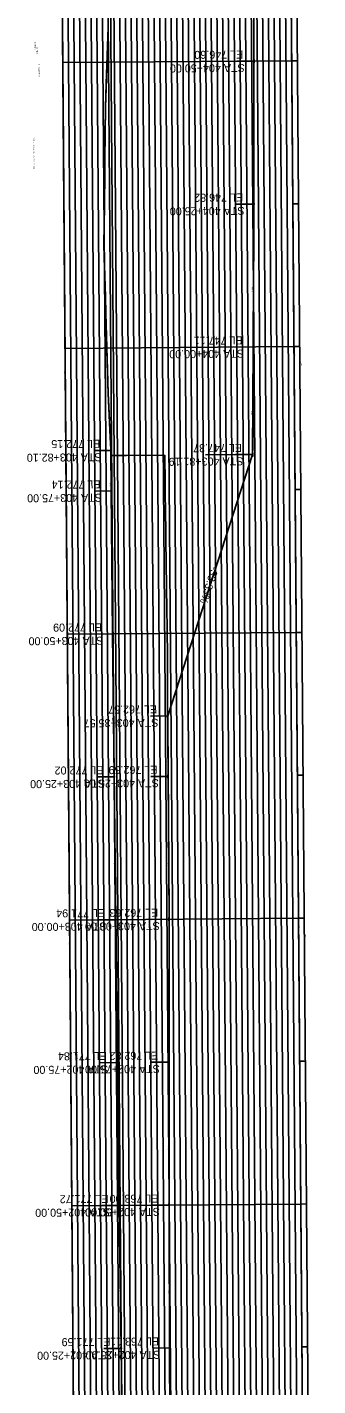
# Model space of a CAD drawing. Extents: x 592274 to 721355, y 141734 to 173089.
# Drawn here: x 593585.6 to 593636.4, y 171859.7 to 172097.4 of the extents above; entities that cross this region are included whole.
import ezdxf

# ---------------------------------------------------------------- set-up
doc = ezdxf.new("R2010")
doc.units = 0
for name, color, linetype in [('B_MISC', 7, 'Continuous'), ('E_PROF_Grid', 7, 'Continuous'), ('E_PROF_GridMin', 7, 'Continuous'), ('P_E_PROF', 7, 'Continuous'), ('P_PROF', 7, 'Continuous'), ('P_PROF_Reference', 7, 'Continuous'), ('P_PROF_Text', 7, 'Continuous'), ('P_PROF_VPINotes', 7, 'Continuous')]:
    doc.layers.add(name, color=color, linetype=linetype)

msp = doc.modelspace()

# ---------------------------------------------------------------- linework, layer by layer
at = {"layer": 'B_MISC'}
msp.add_line((593598.32, 172330.8), (593603.79, 171641.29), dxfattribs=at)
at = {"layer": 'E_PROF_Grid'}
msp.add_lwpolyline([(593636.37, 171641.54), (593629.11, 172558.84), (593628.11, 172558.83), (593635.37, 171641.54)], close=True, dxfattribs=at)
for points in [[(593595.38, 171641.22), (593588.25, 172541.19)], [(593605.37, 171641.3), (593598.25, 172541.27)], [(593615.37, 171641.38), (593608.24, 172541.35)], [(593625.37, 171641.46), (593618.24, 172541.43)], [(593635.37, 171641.54), (593628.24, 172541.51)], [(593632.21, 172041.52), (593592.21, 172041.21)], [(593633.21, 172041.53), (593632.21, 172041.52)], [(593633.21, 172041.53), (593632.21, 172041.52)], [(593633.21, 172041.53), (593632.21, 172041.52)], [(593633, 171941.53), (593593, 171941.21)], [(593634, 171941.54), (593633, 171941.53)], [(593634, 171941.54), (593633, 171941.53)], [(593634, 171941.54), (593633, 171941.53)]]:
    msp.add_lwpolyline(points, dxfattribs=at)
at = {"layer": 'E_PROF_GridMin'}
for points in [[(593596.38, 171641.23), (593589.25, 172541.2)], [(593597.37, 171641.24), (593590.25, 172541.21)], [(593598.37, 171641.24), (593591.25, 172541.22)], [(593599.37, 171641.25), (593592.25, 172541.22)], [(593600.37, 171641.26), (593593.25, 172541.23)], [(593601.37, 171641.27), (593594.25, 172541.24)], [(593602.37, 171641.28), (593595.25, 172541.25)], [(593603.37, 171641.28), (593596.25, 172541.26)], [(593604.37, 171641.29), (593597.25, 172541.26)], [(593606.37, 171641.31), (593599.25, 172541.28)], [(593607.37, 171641.32), (593600.25, 172541.29)], [(593608.37, 171641.32), (593601.25, 172541.29)], [(593609.37, 171641.33), (593602.25, 172541.3)], [(593610.37, 171641.34), (593603.25, 172541.31)], [(593611.37, 171641.35), (593604.25, 172541.32)], [(593612.37, 171641.35), (593605.24, 172541.33)], [(593613.37, 171641.36), (593606.24, 172541.33)], [(593614.37, 171641.37), (593607.24, 172541.34)], [(593616.37, 171641.39), (593609.24, 172541.36)], [(593617.37, 171641.39), (593610.24, 172541.37)], [(593618.37, 171641.4), (593611.24, 172541.37)], [(593619.37, 171641.41), (593612.24, 172541.38)], [(593620.37, 171641.42), (593613.24, 172541.39)], [(593621.37, 171641.43), (593614.24, 172541.4)], [(593622.37, 171641.43), (593615.24, 172541.41)], [(593623.37, 171641.44), (593616.24, 172541.41)], [(593624.37, 171641.45), (593617.24, 172541.42)], [(593626.37, 171641.47), (593619.24, 172541.44)], [(593627.37, 171641.47), (593620.24, 172541.45)], [(593628.37, 171641.48), (593621.24, 172541.45)], [(593629.37, 171641.49), (593622.24, 172541.46)], [(593630.37, 171641.5), (593623.24, 172541.47)], [(593631.37, 171641.51), (593624.24, 172541.48)], [(593632.37, 171641.51), (593625.24, 172541.48)], [(593633.37, 171641.52), (593626.24, 172541.49)], [(593634.37, 171641.53), (593627.24, 172541.5)], [(593631.81, 172091.52), (593591.81, 172091.21)], [(593632.81, 172091.53), (593631.81, 172091.52)], [(593633.01, 172066.53), (593632.01, 172066.52)], [(593633.4, 172016.53), (593632.4, 172016.53)], [(593632.6, 171991.53), (593592.6, 171991.21)], [(593633.6, 171991.53), (593632.6, 171991.53)], [(593633.8, 171966.53), (593632.8, 171966.53)], [(593634.2, 171916.54), (593633.2, 171916.53)], [(593633.39, 171891.53), (593593.39, 171891.21)], [(593634.39, 171891.54), (593633.39, 171891.53)], [(593634.59, 171866.54), (593633.59, 171866.53)]]:
    msp.add_lwpolyline(points, dxfattribs=at)
at = {"layer": 'P_E_PROF'}
for points in [[(593599.39, 172086.68), (593599.73, 172097.41)], [(593599.41, 172087.48), (593599.73, 172097.41)], [(593599.73, 172097.41), (593599.71, 172099.18)], [(593625.21, 172093.96), (593625.21, 172098.96)], [(593625.21, 172088.96), (593625.21, 172093.96)], [(593625.21, 172083.96), (593625.21, 172088.96)], [(593599.28, 172083.4), (593599.41, 172087.48)], [(593599.28, 172083.4), (593599.39, 172086.68)], [(593599.17, 172074.21), (593599.28, 172083.4)], [(593599.18, 172074.9), (593599.28, 172083.4)], [(593625.21, 172078.95), (593625.21, 172083.96)], [(593625.2, 172073.95), (593625.21, 172078.95)], [(593599.13, 172071.4), (593599.18, 172074.9)], [(593599.14, 172071.4), (593599.17, 172074.21)], [(593625.19, 172068.95), (593625.2, 172073.95)], [(593599.02, 172062.21), (593599.14, 172071.4)], [(593599.03, 172062.9), (593599.13, 172071.4)], [(593625.18, 172063.95), (593625.19, 172068.95)], [(593598.99, 172059.4), (593599.03, 172062.9)], [(593598.99, 172059.4), (593599.02, 172062.21)], [(593625.17, 172058.94), (593625.18, 172063.95)], [(593599.23, 172050.9), (593598.99, 172059.4)], [(593599.25, 172050.21), (593598.99, 172059.4)], [(593625.15, 172053.94), (593625.17, 172058.94)], [(593625.13, 172048.94), (593625.15, 172053.94)], [(593599.32, 172047.4), (593599.23, 172050.9)], [(593599.33, 172047.4), (593599.25, 172050.21)], [(593625.11, 172043.94), (593625.13, 172048.94)], [(593599.6, 172037.48), (593599.32, 172047.4)], [(593599.62, 172036.68), (593599.33, 172047.4)], [(593625.08, 172038.93), (593625.11, 172043.94)], [(593625.06, 172033.93), (593625.08, 172038.93)], [(593599.71, 172033.41), (593599.6, 172037.48)], [(593599.72, 172033.41), (593599.62, 172036.68)], [(593600.09, 172025.65), (593599.71, 172033.41)], [(593600.12, 172025.02), (593599.72, 172033.41)], [(593625.03, 172028.93), (593625.06, 172033.93)], [(593624.99, 172023.92), (593625.03, 172028.93)], [(593600.24, 172022.46), (593600.09, 172025.65)], [(593600.2, 172023.41), (593600.12, 172025.02)], [(593624.98, 172022.66), (593624.99, 172023.92)], [(593600.23, 172018.97), (593600.2, 172023.41)], [(593602.96, 172022.48), (593600.24, 172022.46)], [(593609.63, 172022.53), (593602.96, 172022.48)], [(593609.63, 172022.51), (593609.63, 172022.53)], [(593609.69, 172017.64), (593609.63, 172022.51)], [(593616.73, 172022.59), (593624.98, 172022.66)], [(593600.25, 172017.49), (593600.23, 172018.97)], [(593600.31, 172011.46), (593600.25, 172017.49)], [(593609.69, 172017.56), (593609.69, 172017.64)], [(593609.78, 172010.99), (593609.69, 172017.56)], [(593600.31, 172010.89), (593600.31, 172011.46)], [(593600.32, 172010.6), (593600.31, 172010.89)], [(593600.35, 172007.63), (593600.32, 172010.6)], [(593609.79, 172010.96), (593609.78, 172010.99)], [(593609.83, 172007.72), (593609.79, 172010.96)], [(593600.36, 172006.56), (593600.35, 172007.63)], [(593609.83, 172007.7), (593609.83, 172007.72)], [(593610, 171995.42), (593609.83, 172007.7)], [(593600.47, 171995.3), (593600.36, 172006.56)], [(593600.5, 171992.73), (593600.47, 171995.3)], [(593610, 171995.37), (593610, 171995.42)], [(593610.04, 171992.58), (593610, 171995.37)], [(593600.5, 171992.49), (593600.5, 171992.73)], [(593600.5, 171991.99), (593600.5, 171992.49)], [(593600.56, 171986.72), (593600.5, 171991.99)], [(593610.04, 171992.57), (593610.04, 171992.58)], [(593610.04, 171992.54), (593610.04, 171992.57)], [(593610.08, 171986.79), (593610.04, 171992.54)], [(593600.56, 171986.38), (593600.56, 171986.72)], [(593600.6, 171982.79), (593600.56, 171986.38)], [(593610.08, 171986.78), (593610.08, 171986.79)], [(593610.1, 171982.86), (593610.08, 171986.78)], [(593600.71, 171972.31), (593600.6, 171982.79)], [(593610.1, 171982.81), (593610.1, 171982.86)], [(593610.18, 171971.4), (593610.1, 171982.81)], [(593600.72, 171971.32), (593600.71, 171972.31)], [(593610.18, 171971.38), (593610.18, 171971.4)], [(593600.73, 171970.99), (593600.72, 171971.32)], [(593600.77, 171967.49), (593600.73, 171970.99)], [(593610.2, 171967.57), (593610.18, 171971.38)], [(593601.02, 171944.68), (593600.77, 171967.49)], [(593610.2, 171967.46), (593610.2, 171967.57)], [(593610.37, 171942.59), (593610.2, 171967.46)], [(593601.05, 171942.51), (593601.02, 171944.68)], [(593601.05, 171942.49), (593601.05, 171942.51)], [(593601.05, 171942.51), (593601.05, 171942.51)], [(593601.25, 171925.41), (593601.05, 171942.49)], [(593610.37, 171942.57), (593610.37, 171942.59)], [(593610.37, 171942.59), (593610.37, 171942.59)], [(593610.37, 171942.49), (593610.37, 171942.57)], [(593610.38, 171923.86), (593610.37, 171942.49)], [(593601.27, 171923.79), (593601.25, 171925.41)], [(593610.38, 171923.84), (593610.38, 171923.86)], [(593601.27, 171923.25), (593601.27, 171923.79)], [(593601.34, 171917.5), (593601.27, 171923.25)], [(593610.38, 171917.57), (593610.38, 171923.84)], [(593601.63, 171894.67), (593601.34, 171917.5)], [(593610.38, 171917.46), (593610.38, 171917.57)], [(593610.38, 171892.57), (593610.38, 171917.46)], [(593601.66, 171892.5), (593601.63, 171894.67)], [(593601.66, 171892.14), (593601.66, 171892.5)], [(593601.71, 171888.39), (593601.66, 171892.14)], [(593610.38, 171892.55), (593610.38, 171892.57)], [(593610.4, 171888.46), (593610.38, 171892.55)], [(593601.71, 171888.05), (593601.71, 171888.39)], [(593610.4, 171888.08), (593610.4, 171888.46)], [(593610.4, 171888.46), (593610.4, 171888.46)], [(593601.71, 171888.02), (593601.71, 171888.05)], [(593601.71, 171887.98), (593601.71, 171888.02)], [(593601.72, 171887.58), (593601.71, 171887.98)], [(593601.74, 171885.84), (593601.72, 171887.58)], [(593601.98, 171867.5), (593601.74, 171885.84)], [(593610.4, 171887.65), (593610.4, 171888.08)], [(593610.4, 171888.08), (593610.4, 171888.08)], [(593610.4, 171887.56), (593610.4, 171887.65)], [(593610.48, 171867.57), (593610.4, 171887.56)], [(593602, 171866.61), (593601.98, 171867.5)], [(593610.48, 171867.56), (593610.48, 171867.57)], [(593610.48, 171866.59), (593610.48, 171867.56)], [(593602, 171866.53), (593602, 171866.61)], [(593602.44, 171834.35), (593602, 171866.53)], [(593610.48, 171866.54), (593610.48, 171866.59)], [(593610.48, 171866.59), (593610.48, 171866.59)], [(593610.48, 171866.59), (593610.48, 171866.59)], [(593610.52, 171855.19), (593610.48, 171866.54)]]:
    msp.add_lwpolyline(points, dxfattribs=at)
at = {"layer": 'P_PROF'}
for points in [[(593625.21, 172091.47), (593625.17, 172116.47)], [(593625.19, 172066.47), (593625.21, 172091.47)], [(593625.1, 172041.47), (593625.19, 172066.47)], [(593624.98, 172022.66), (593625.1, 172041.47)], [(593600.26, 172016.27), (593600.2, 172023.37)], [(593610.14, 171976.92), (593624.98, 172022.66)], [(593600.51, 171991.27), (593600.26, 172016.27)], [(593600.78, 171966.27), (593600.51, 171991.27)], [(593610.21, 171966.35), (593610.14, 171976.92)], [(593601.06, 171941.27), (593600.78, 171966.27)], [(593610.37, 171941.35), (593610.21, 171966.35)], [(593601.36, 171916.28), (593601.06, 171941.27)], [(593610.38, 171916.35), (593610.37, 171941.35)], [(593601.67, 171891.28), (593601.36, 171916.28)], [(593610.39, 171891.35), (593610.38, 171916.35)], [(593602, 171866.28), (593601.67, 171891.28)], [(593610.48, 171866.35), (593610.39, 171891.35)], [(593602.35, 171841.28), (593602, 171866.28)], [(593610.57, 171841.35), (593610.48, 171866.35)]]:
    msp.add_lwpolyline(points, dxfattribs=at)
at = {"layer": 'P_PROF_Reference'}
for points in [[(593595.38, 171641.22), (593588.11, 172558.51)], [(593635.37, 171641.54), (593628.11, 172558.83)], [(593632.28, 172041.52), (593632.14, 172041.52)], [(593633.07, 171941.53), (593632.93, 171941.53)]]:
    msp.add_lwpolyline(points, dxfattribs=at)
at = {"layer": 'P_PROF_VPINotes'}
for points in [[(593625.21, 172091.47), (593622.21, 172091.45)], [(593625.19, 172066.47), (593622.19, 172066.45)], [(593625.1, 172041.47), (593622.1, 172041.44)], [(593600.2, 172023.37), (593597.2, 172023.35)], [(593624.98, 172022.66), (593621.98, 172022.63)], [(593600.26, 172016.27), (593597.26, 172016.25)], [(593600.51, 171991.27), (593597.51, 171991.25)], [(593610.14, 171976.92), (593607.14, 171976.9)], [(593600.78, 171966.27), (593597.78, 171966.25)], [(593610.21, 171966.35), (593607.21, 171966.32)], [(593601.06, 171941.27), (593598.06, 171941.25)], [(593610.37, 171941.35), (593607.37, 171941.32)], [(593601.36, 171916.28), (593598.36, 171916.25)], [(593610.38, 171916.35), (593607.38, 171916.32)], [(593601.67, 171891.28), (593598.67, 171891.25)], [(593610.39, 171891.35), (593607.39, 171891.32)], [(593602, 171866.28), (593599, 171866.26)], [(593610.48, 171866.35), (593607.48, 171866.32)]]:
    msp.add_lwpolyline(points, dxfattribs=at)
for centre in [(593625.21, 172091.47), (593625.19, 172066.47), (593625.1, 172041.47), (593600.2, 172023.37), (593624.98, 172022.66), (593600.26, 172016.27), (593600.51, 171991.27), (593610.14, 171976.92), (593610.21, 171966.35), (593600.78, 171966.27), (593601.06, 171941.27), (593610.37, 171941.35), (593601.36, 171916.28), (593610.38, 171916.35), (593601.67, 171891.28), (593610.39, 171891.35), (593602, 171866.28), (593610.48, 171866.35)]:
    msp.add_ellipse(centre, major_axis=(-0.003, 0.35), ratio=0.1, dxfattribs=at)

# ---------------------------------------------------------------- texts
at = {"layer": 'P_PROF_Reference'}
for s, height, p in [('V Scale : 2', 0.2, (593587.05, 172093.49)), ('H Scale : 20', 0.2, (593587.41, 172092.44)), ('Exaggeration : 10', 0.2, (593587.77, 172088.81)), ('Profile View of  BOTTOM OF WALL R-51-50', 0.2, (593586.87, 172072.64)), ('404', 0.14, (593632.43, 172039.86)), ('404+00.00', 0.14, (593592.17, 172036.49)), ('403', 0.14, (593633.22, 171939.9)), ('403+00.00', 0.14, (593592.96, 171936.49))]:
    msp.add_text(s, height=height, rotation=90.4539, dxfattribs=at).set_placement(p)
at = {"layer": 'P_PROF_Text'}
for s, p in [('404+00', (593633.55, 172038.2)), ('403+00', (593634.34, 171938.21))]:
    msp.add_text(s, height=0.14, rotation=90.4539, dxfattribs=at).set_placement(p)
at = {"layer": 'P_PROF_VPINotes'}
for s, height, rotation, p in [('EL 746.60', 1.4, 180.4539, (593623.34, 172093.33)), ('STA 404+50.00', 1.4, 180.4539, (593623.59, 172090.98)), ('-0.90%', 0.187, 89.9393, (593625.09, 172076.01)), ('EL 746.82', 1.4, 180.4539, (593623.31, 172068.32)), ('STA 404+25.00', 1.4, 180.4539, (593623.56, 172065.98)), ('-1.16%', 0.213, 89.7908, (593625.03, 172051.05)), ('EL 747.11', 1.4, 180.4539, (593623.22, 172043.32)), ('STA 404+00.00', 1.4, 180.4539, (593623.47, 172040.99)), ('-1.38%', 0.237, 89.6618, (593624.92, 172029.17)), ('EL 772.15', 1.4, 180.4539, (593598.32, 172025.23)), ('EL 747.37', 1.4, 180.4539, (593623.11, 172024.51)), ('STA 403+82.10', 1.4, 180.4539, (593598.57, 172022.88)), ('STA 403+81.19', 1.4, 180.4539, (593623.35, 172022.17)), ('EL 772.14', 1.4, 180.4539, (593598.39, 172018.13)), ('0.12%', 0.141, 90.5224, (593600.15, 172017.08)), ('STA 403+75.00', 1.4, 180.4539, (593598.63, 172015.79)), ('-33.33%', 1.342, 252.0189, (593617.81, 172003.17)), ('0.21%', 0.143, 90.5756, (593600.31, 172001.02)), ('EL 772.09', 1.4, 180.4539, (593598.64, 171993.13)), ('STA 403+50.00', 1.4, 180.4539, (593598.88, 171990.78)), ('EL 762.57', 1.4, 180.4539, (593608.27, 171978.78)), ('STA 403+35.57', 1.4, 180.4539, (593608.51, 171976.43)), ('0.28%', 0.145, 90.612, (593600.57, 171976.02)), ('-0.13%', 0.141, 90.3804, (593610.09, 171968.59)), ('EL 772.02', 1.4, 180.4539, (593598.9, 171968.13)), ('EL 762.59', 1.4, 180.4539, (593608.34, 171968.2)), ('STA 403+25.00', 1.4, 180.4539, (593599.15, 171965.78)), ('STA 403+25.00', 1.4, 180.4539, (593608.58, 171965.86)), ('0.34%', 0.148, 90.6468, (593600.85, 171951.01)), ('-0.16%', 0.142, 90.3627, (593610.21, 171950.8)), ('EL 771.94', 1.4, 180.4539, (593599.19, 171943.13)), ('EL 762.63', 1.4, 180.4539, (593608.49, 171943.2)), ('STA 403+00.00', 1.4, 180.4539, (593599.43, 171940.79)), ('STA 403+00.00', 1.4, 180.4539, (593608.74, 171940.86)), ('0.40%', 0.151, 90.6829, (593601.14, 171926.01)), ('-0.76%', 0.175, 90.018, (593610.27, 171925.87)), ('EL 771.84', 1.4, 180.4539, (593599.49, 171918.13)), ('EL 762.82', 1.4, 180.4539, (593608.5, 171918.2)), ('STA 402+75.00', 1.4, 180.4539, (593599.73, 171915.79)), ('STA 402+75.00', 1.4, 180.4539, (593608.75, 171915.86)), ('0.46%', 0.154, 90.7177, (593601.45, 171901.01)), ('-0.74%', 0.174, 90.0272, (593610.28, 171900.87)), ('EL 771.72', 1.4, 180.4539, (593599.8, 171893.14)), ('EL 763.00', 1.4, 180.4539, (593608.52, 171893.2)), ('STA 402+50.00', 1.4, 180.4539, (593600.04, 171890.79)), ('STA 402+50.00', 1.4, 180.4539, (593608.76, 171890.86)), ('0.52%', 0.158, 90.7542, (593601.77, 171876)), ('-0.43%', 0.152, 90.2088, (593610.34, 171875.83)), ('EL 771.59', 1.4, 180.4539, (593600.13, 171868.13)), ('EL 763.11', 1.4, 180.4539, (593608.61, 171868.2)), ('STA 402+25.00', 1.4, 180.4539, (593600.37, 171865.79)), ('STA 402+25.00', 1.4, 180.4539, (593608.85, 171865.86))]:
    msp.add_text(s, height=height, rotation=rotation, dxfattribs=at).set_placement(p)

doc.saveas('drawing.dxf')
